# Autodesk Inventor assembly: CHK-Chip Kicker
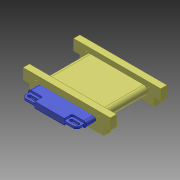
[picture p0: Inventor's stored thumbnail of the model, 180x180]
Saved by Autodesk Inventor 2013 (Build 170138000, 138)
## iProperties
Created: 2013-03
Part Number: CHK-Chip Kicker
Document SubType Name: Assembly
Designer: rYan
Author: rYan
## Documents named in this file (3)
- E:\Tigers SVN\mechanik\2013\Inventor\Checks\CHK-Chip Kicker.iam
- E:\Tigers SVN\mechanik\2013\Inventor\Kicker\Chip\Chip Spulenkoerper.ipt
- E:\Tigers SVN\mechanik\2013\Inventor\Kicker\Chip\Chip Stoessel.ipt
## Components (2 placed, 2 different names)
1. Chip Spulenkörper:1 — Mate:1, Mate:2
2. Chip Stoessel:1 — Mate:1, Mate:2
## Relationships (2: Mate 2)
- Mate:1: Chip Spulenkörper:1 ↔ Chip Stoessel:1
- Mate:2: Chip Spulenkörper:1 ↔ Chip Stoessel:1
